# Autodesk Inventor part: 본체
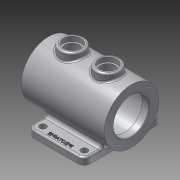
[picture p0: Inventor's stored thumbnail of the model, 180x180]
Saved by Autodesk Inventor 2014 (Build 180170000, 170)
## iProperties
Created: 2014-12
Part Number: 본체
Material: 알루미늄 6061
Document SubType Name: Modeling
Designer: Owner
Mass: 1294 g
Surface Area: 1040.12 cm^2
Volume: 477.493 cm^3
Density: 2.71 g/cm^3
Appearance: 알루미늄 - 평지
Author: Owner
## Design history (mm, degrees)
sketch "스케치1"
  geometry: L1 (-70, 0)-(70, 0); L2 (-70, 46)-(70, 46); L3 (-70, 46)-(-70, 30); L4 (-70, 30)-(-58, 30); L5 (-58, 30)-(-58, 37.5); L6 (-58, 37.5)-(58, 37.5); L7 (58, 37.5)-(58, 30); L8 (58, 30)-(70, 30); L9 (70, 30)-(70, 46); 4 further points
  constraints: 18 end point, 4 parallel, 3 midpoint, 2 equal length, 2 horizontal alignment, 2 perpendicular, 2 vertical alignment, 1 coincident, 1 collinear, 1 horizontal
  dimensions: "d0" = 140 distance of L1.start L1.end; "d1" = 92 diameter of L2 L1; "d2" = 12 distance of L7.end L8.end; "d3" = 60 diameter of L8 L1; "d4" = 75 diameter of L6 L1
revolve "회전1" sketch "스케치1" stored, may be unused: angle "d5" = 90 deg
node "작업 평면1"
sketch "스케치2"
  geometry: L1 (-70, -46)-(-70, 46) reference; L2 (70, -46)-(70, 46) reference; C1 r 20 at (-30, 0); C2 r 20 at (30, 0); 1 further point
  constraints: 2 centre point, 2 horizontal alignment
  dimensions: "d7" = 40 diameter of C1; "d8" = 40 diameter of C2; "d9" = 40 distance from line of C1.centre L1; "d10" = 40 distance from line of L2 C2.centre
extrude "돌출1" join sketch "스케치2" stored distance "d11" = 10; taper "d12" = 0 deg
node "작업 평면2"
sketch "스케치3"
  geometry: L1 (50, -65)-(50, 65); L2 (50, -65)-(38, -65); L3 (50, 65)-(38, 65); L4 (38, 65)-(38, 38.884); L5 (38, -65)-(38, -38.884); A1 r 5 centre (33, -38.884) between (38, -38.884) and (29.765, -35.072); A2 r 5 centre (33, 38.884) between (29.765, 35.072) and (38, 38.884); A3 r 46 centre (0, 0) between (29.765, -35.072) and (29.765, 35.072) reference; 2 further points
  constraints: 10 end point, 6 point on circle, 4 tangent, 2 centre point, 2 equal length, 2 perpendicular, 1 horizontal alignment, 1 midpoint, 1 vertical
  dimensions: "d14" = 130 distance of L1.start L1.end; "d15" = 50 distance from line of L1 point (0, 0); "d16" = 12 distance of L1.start L2.end; "d17" = 12 distance of L1.end L3.end; "d18" = 10 diameter of A1; "d19" = 10 diameter of A2
extrude "돌출2" join sketch "스케치3" distance "d20" = 95; taper "d21" = 0 deg
hole "구멍1" diameter "d24" = 25; stored, may be unused: countersink angle "d28" = 90 deg, drill point angle "d30" = 118 deg; dims "d22" = 10, "d23" = 10, "d25" = 6, "d26" = 30, "d27" = 8, "d29" = 8
hole "구멍2" diameter "d33" = 25; stored, may be unused: countersink angle "d37" = 90 deg, drill point angle "d39" = 118 deg; dims "d31" = 10, "d32" = 10, "d34" = 6, "d35" = 30, "d36" = 8, "d38" = 8
sketch "스케치4"
  geometry: L1 (0, 0)-(28.284, 28.284); L2 (0, 0)-(40, 0); C1 r 46 at (0, 0) reference
  constraints: 4 end point, 1 equal length, 1 horizontal
  dimensions: "d40" = 40 distance of L1.start L1.end; "d41" = 45 deg angle of L2 L1
hole "구멍3" sketch "스케치4" at (28.284, 28.284) diameter "d42" = 3.242; stored, may be unused: countersink angle "d46" = 90 deg, drill point angle "d48" = 118 deg; dims "d43" = 8, "d44" = 30, "d45" = 8, "d47" = 10
sketch "스케치5"
  geometry: L1 (0, 26.116)-(0, 0) reference; C1 r 5.5 at (-12.5, 13); C2 r 5.5 at (-82.5, 13); 1 further point
  constraints: 2 centre point, 1 horizontal alignment
  dimensions: "d52" = 11 diameter of C1; "d53" = 12.5 distance from line of L1 C1.centre; "d54" = 52 vertical distance of C1.centre point (-55, 65); "d59" = 11 diameter of C2; "d60" = 70 distance of C1.centre C2.centre
extrude "돌출3" cut sketch "스케치5" stored distance "d57" = 95; taper "d58" = 0 deg
sketch "스케치6"
  geometry: L1 (0, 0)-(-95, 0) reference; C1 r 5.5 at (-12.5, 13) reference; 2 further points
  constraints: 1 other
  dimensions: "d61" = 35 horizontal distance of C1.centre point (-47.5, 8); "d62" = 8 distance from line of L1 point (-47.5, 8)
feature "엠보싱1" sketch "스케치6" dims "d0" = 140, "d1" = 92, "d2" = 12, "d3" = 60, "d4" = 75, "d63" = 1, "d64" = 0
fillet "모깎기1" dims "d65" = 10
fillet "모깎기2" dims "d66" = 3
fillet "모깎기3" dims "d67" = 3
fillet "모깎기4" dims "d68" = 3
fillet "모깎기5" dims "d69" = 3
chamfer "모따기1" distance "d70" = 1; stored, may be unused: second distance "d71" = 2, angle "d72" = 45 deg
node "솔리드1"
pattern_circular "원형 패턴1" dims angle "d50" = 360 deg
mirror "대칭1"
mirror "대칭2"
other parameters: "d6" = 56, "d13" = -15
